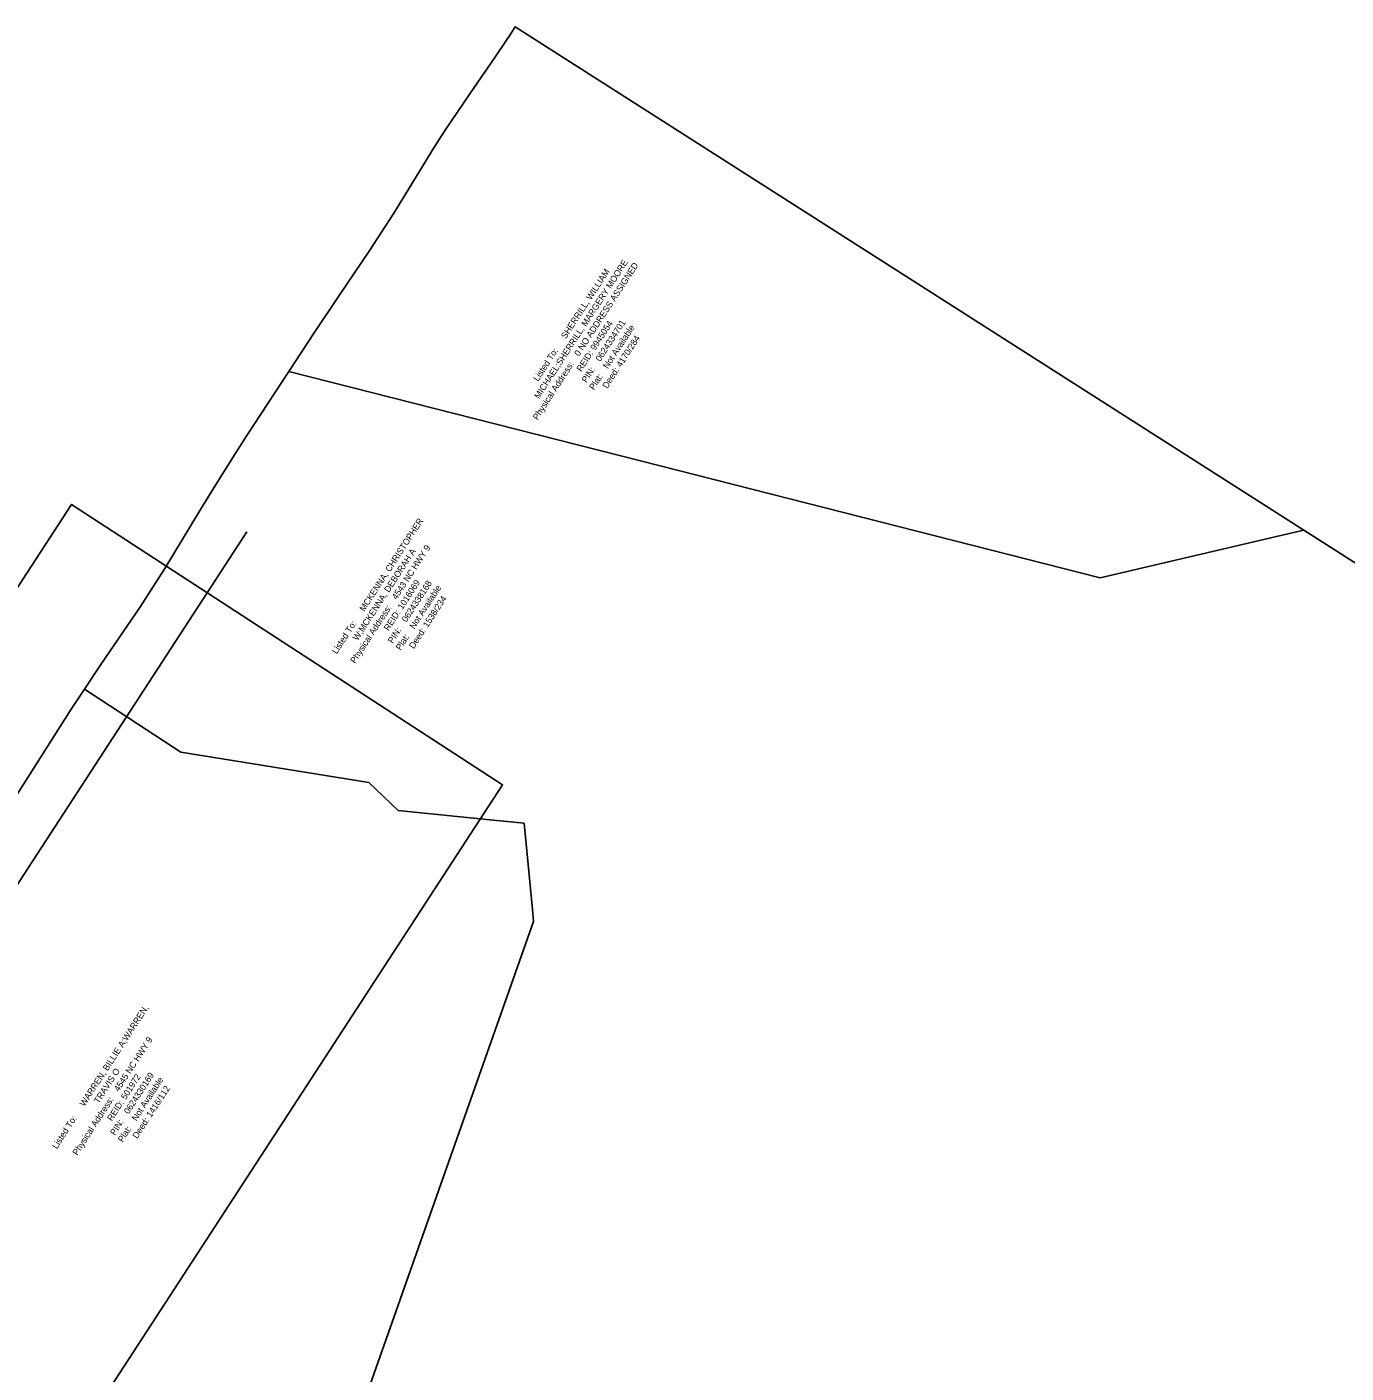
# Model space of a CAD drawing. Extents: x 1019969 to 1024963, y 638146 to 643978.
# Drawn here: x 1023056 to 1023888, y 643129 to 643978 of the extents above; entities that cross this region are included whole.
import ezdxf

# ---------------------------------------------------------------- set-up
doc = ezdxf.new("R2010")
doc.units = 0
for name, color, linetype in [('Pattern 5', 7, 'Continuous'), ('Scratch_Level_2', 7, 'Continuous'), ('Scratch_Level_3', 7, 'Continuous'), ('Scratch_Level_4', 7, 'Continuous')]:
    doc.layers.add(name, color=color, linetype=linetype)

msp = doc.modelspace()

# ---------------------------------------------------------------- linework, layer by layer
at = {"layer": 'Scratch_Level_2'}
msp.add_lwpolyline([(1022778.99, 643208.83), (1023083.87, 643677.31), (1023355.75, 643500.37), (1023050.87, 643031.89)], close=True, dxfattribs=at)
at = {"layer": 'Scratch_Level_3'}
msp.add_line((1022857.7, 643142.64), (1023194.35, 643659.93), dxfattribs=at)
at = {"layer": 'Scratch_Level_4'}
for points in [[(1023861.31, 643661.12), (1023850.29, 643658.54), (1023732.69, 643631), (1023442.81, 643704.75), (1023442.73, 643704.78), (1023221, 643761.19), (1023237, 643785.56), (1023252.31, 643808.55), (1023272, 643837.62), (1023279.38, 643848.94), (1023287.19, 643861.12), (1023294.63, 643873), (1023312.38, 643902.31), (1023319.13, 643912.81), (1023335.5, 643937), (1023350.87, 643959.19), (1023358.62, 643970.69), (1023359.64, 643972.29), (1023363.62, 643978.5)], [(1023375.37, 643414.25), (1023232.66, 643010.18), (1023186.87, 643033.19), (1022911.81, 643171.25), (1022876.86, 643225.56), (1022887.12, 643241.44), (1022914.18, 643282.44), (1022923.5, 643296.94), (1022932.63, 643311.19), (1022953.13, 643345.06), (1022956.89, 643351.1), (1022968.88, 643370.44), (1022986.68, 643397.63), (1023009.31, 643431.38), (1023083.62, 643548.06), (1023092.12, 643560.81), (1023152.81, 643521), (1023271.39, 643501.81), (1023289.88, 643484.25), (1023349.85, 643478.2), (1023369.37, 643476.25), (1023374.6, 643421.76)]]:
    msp.add_lwpolyline(points, close=True, dxfattribs=at)
msp.add_lwpolyline([(1023232.66, 643010.18), (1023375.37, 643414.25), (1023374.6, 643421.76), (1023369.37, 643476.25), (1023349.85, 643478.2), (1023289.88, 643484.25), (1023271.39, 643501.81), (1023152.81, 643521), (1023092.12, 643560.81), (1023102.31, 643576.31), (1023127.31, 643613), (1023135.19, 643625.06), (1023142.69, 643636.94), (1023165.19, 643674.12), (1023173.63, 643687.81), (1023187.19, 643709.25), (1023194.37, 643720.69), (1023221, 643761.19), (1023442.73, 643704.78), (1023442.81, 643704.75), (1023732.69, 643631), (1023850.29, 643658.54), (1023861.31, 643661.12), (1024075.31, 643524.69)], dxfattribs=at)

# ---------------------------------------------------------------- texts
at = {"layer": 'Pattern 5'}
for s, rotation, p in [('MICHAEL;SHERRILL, MARGERY MOORE', 56.94406, (1023378.8, 643743.59)), ('SHERRILL, WILLIAM ', 56.94406, (1023395.67, 643781.43)), ('0 NO ADDRESS ASSIGNED', 56.94406, (1023404.04, 643770.46)), ('9945054', 56.94406, (1023414.17, 643774.11)), ('0624334701', 56.94406, (1023417.41, 643767.15)), ('Not Available', 56.94406, (1023422.17, 643762.55)), ('4170/284', 56.94406, (1023430.54, 643763.51)), ('Listed To:', 56.94406, (1023378.22, 643754.61)), ('REID:', 56.94406, (1023405.45, 643760.7)), ('Physical Address:', 56.94406, (1023377.86, 643730.23)), ('PIN:', 56.94406, (1023408.68, 643753.74)), ('Deed:', 56.94406, (1023421.81, 643750.1)), ('Plat:', 56.94406, (1023413.44, 643749.14)), ('MCKENNA, CHRISTOPHER ', 56.94406, (1023268.56, 643609.43)), ('4543 NC HWY 9', 56.94406, (1023288.94, 643616.91)), ('W;MCKENNA, DEBORAH A', 56.94406, (1023264.34, 643591.03)), ('1016069', 56.94406, (1023292.62, 643610.65)), ('0624338168', 56.94406, (1023295.2, 643602.7)), ('Not Available', 56.94406, (1023300.13, 643598.35)), ('1538/234', 56.94406, (1023308.51, 643599.31)), ('Physical Address:', 56.94406, (1023262.76, 643576.68)), ('REID:', 56.94406, (1023283.89, 643597.24)), ('Listed To:', 56.94406, (1023251.11, 643582.61)), ('PIN:', 56.94406, (1023286.47, 643589.29)), ('Plat:', 56.94406, (1023291.4, 643584.94)), ('Deed:', 56.94406, (1023299.78, 643585.9)), ('WARREN, BILLIE A;WARREN, ', 56.99063, (1023092.07, 643297.23)), ('4545 NC HWY 9', 56.99063, (1023113.66, 643306.61)), ('TRAVIS O', 56.99063, (1023101.02, 643299.08)), ('501972', 56.99063, (1023118.05, 643301.42)), ('0624330169', 56.99063, (1023119.95, 643292.42)), ('Not Available', 56.99063, (1023124.87, 643288.06)), ('1416/112', 56.99063, (1023134.08, 643290.31)), ('Physical Address:', 56.99063, (1023087.52, 643266.35)), ('REID:', 56.99063, (1023109.33, 643288.01)), ('Listed To:', 56.99063, (1023074.64, 643270.4)), ('PIN:', 56.99063, (1023111.24, 643279)), ('Deed:', 56.99063, (1023125.37, 643276.89)), ('Plat:', 56.99063, (1023116.15, 643274.64))]:
    msp.add_text(s, height=4, rotation=rotation, dxfattribs=at).set_placement(p)

doc.saveas('drawing.dxf')
